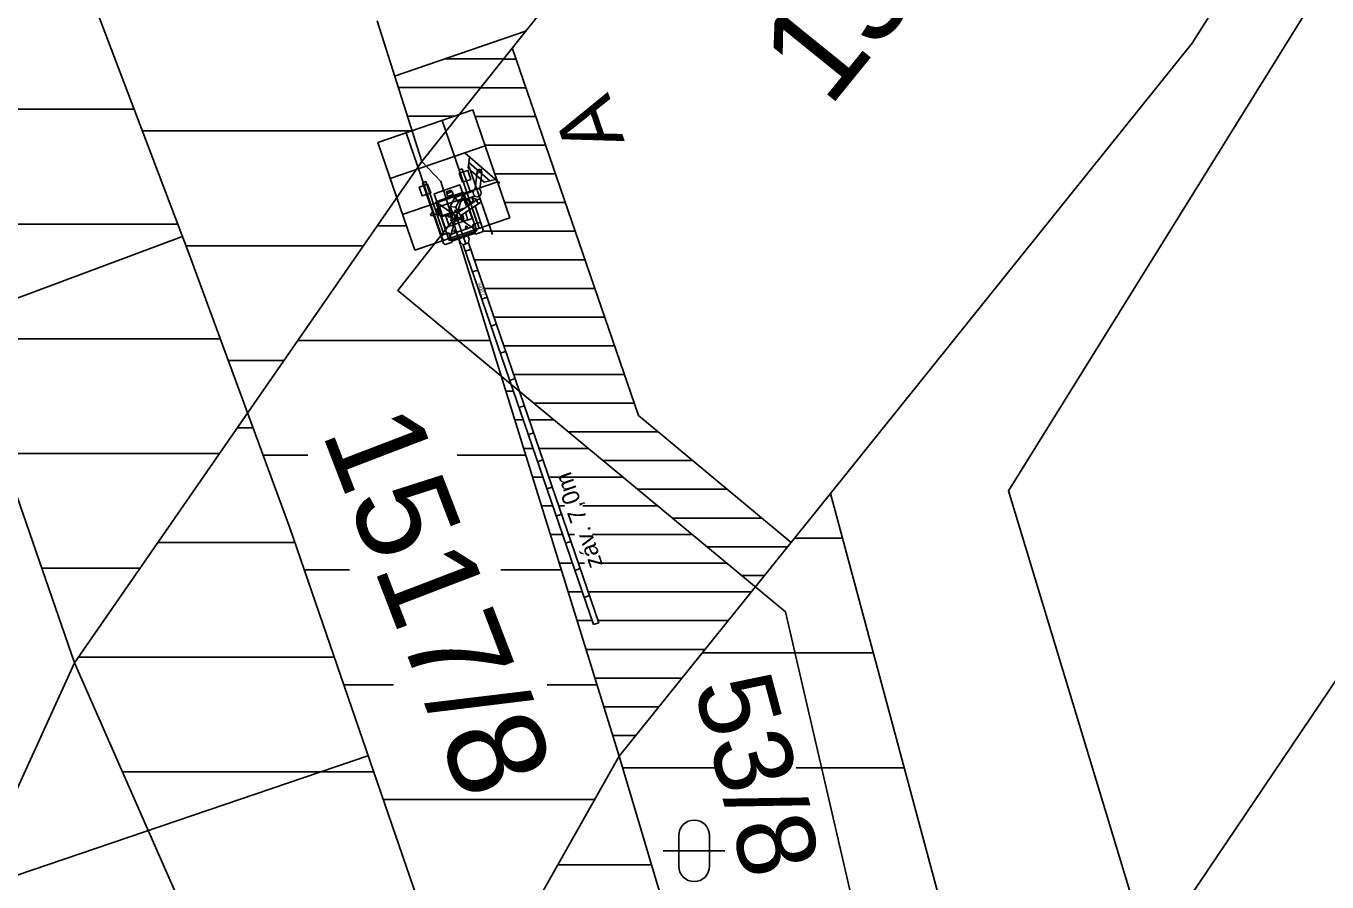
# Model space of a CAD drawing. Extents: x -553916 to -552953, y -1067470 to -1066637.
# Drawn here: x -553520.24 to -553497.58, y -1066983.52 to -1066968.6 of the extents above; entities that cross this region are included whole.
import ezdxf

# ---------------------------------------------------------------- set-up
doc = ezdxf.new("R2010")
doc.units = 0
for name, color, linetype in [('Hranice parcel', 7, 'Continuous'), ('Kolej', 7, 'Continuous'), ('Nová kabelizace', 7, 'Continuous'), ('nové prvky ZZ', 7, 'Continuous'), ('Parcelní čísla', 7, 'Continuous'), ('Propustek', 7, 'Continuous'), ('Přejezd - štěrkové lože', 7, 'Continuous'), ('trasa_NN_popisky', 7, 'Continuous'), ('Vrstva 1', 7, 'Continuous'), ('Vrstva 58', 7, 'Continuous'), ('Značky kultur', 7, 'Continuous')]:
    doc.layers.add(name, color=color, linetype=linetype)

msp = doc.modelspace()

# ---------------------------------------------------------------- linework, layer by layer
at = {"layer": 'Hranice parcel'}
for p, q in [((-553486.47, -1066947.45), (-553499.93, -1066968.9)), ((-553499.93, -1066968.9), (-553506.23, -1066976.75)), ((-553519.4, -1066979.7), (-553528.66, -1067000.03))]:
    msp.add_line(p, q, dxfattribs=at)
for points in [[(-553489.9, -1066939.2), (-553506.21, -1066961.59), (-553507.62, -1066963.64), (-553510.49, -1066967.37), (-553513.35, -1066970.96)], [(-553481.25, -1066991.64), (-553501.02, -1066983.66), (-553503.13, -1066976.7), (-553485.37, -1066948.09)]]:
    msp.add_lwpolyline(points, dxfattribs=at)
at = {"layer": 'Kolej'}
msp.add_lwpolyline([(-553503.324, -1067065.808), (-553502.678, -1067054.027), (-553502.762, -1067041.504), (-553503.626, -1067029.057), (-553504.756, -1067019.974), (-553506.183, -1067011.388), (-553508.328, -1067001.388), (-553510.948, -1066991.622), (-553512.921, -1066985.291), (-553515.647, -1066977.347), (-553517.422, -1066972.53), (-553519.157, -1066967.95), (-553522.886, -1066958.375), (-553529.101, -1066942.549), (-553538.686, -1066918.107), (-553542.908, -1066907.329), (-553546.692, -1066897.676), (-553555.025, -1066876.441), (-553564.644, -1066851.894), (-553574.241, -1066827.427), (-553583.19, -1066804.618)], dxfattribs=at)
at = {"layer": 'Nová kabelizace'}
msp.add_line((-553505.478, -1066985.448), (-553507.017, -1066978.813), dxfattribs=at)
for points in [[(-553507.017, -1066978.813), (-553513.769, -1066973.209), (-553512.749, -1066971.917)], [(-553506.913, -1066977.6), (-553509.575, -1066975.39)]]:
    msp.add_lwpolyline(points, dxfattribs=at)
at = {"layer": 'nové prvky ZZ'}
for p, q in [((-553512.461, -1066970.063), (-553514.116, -1066970.631)), ((-553512.461, -1066970.063), (-553511.816, -1066971.941)), ((-553512.349, -1066972.124), (-553512.993, -1066970.246)), ((-553512.975, -1066972.339), (-553513.62, -1066970.461)), ((-553514.116, -1066970.631), (-553513.471, -1066972.509)), ((-553512.246, -1066970.689), (-553513.901, -1066971.257)), ((-553512.595, -1066970.814), (-553511.991, -1066971.338)), ((-553512.52, -1066970.88), (-553512.54, -1066971.079)), ((-553512.53, -1066970.979), (-553512.163, -1066971.297)), ((-553512.528, -1066971.045), (-553512.119, -1066972.237)), ((-553512.7, -1066971.109), (-553512.644, -1066971.09)), ((-553512.56, -1066971.518), (-553512.7, -1066971.109)), ((-553512.504, -1066971.499), (-553512.644, -1066971.09)), ((-553512.54, -1066971.079), (-553512.261, -1066971.321)), ((-553512.385, -1066971.135), (-553512.421, -1066971.443)), ((-553512.293, -1066971.076), (-553512.4, -1066971.2)), ((-553512.355, -1066971.139), (-553512.338, -1066971.137)), ((-553512.345, -1066971.146), (-553512.348, -1066971.13)), ((-553512.306, -1066971.145), (-553512.341, -1066971.451)), ((-553512.066, -1066971.273), (-553512.261, -1066971.321)), ((-553512.031, -1066971.315), (-553513.686, -1066971.883)), ((-553513.282, -1066971.308), (-553513.337, -1066971.328)), ((-553512.971, -1066972.394), (-553513.337, -1066971.328)), ((-553512.964, -1066972.234), (-553513.282, -1066971.308)), ((-553513.106, -1066971.666), (-553512.624, -1066971.499)), ((-553513.05, -1066971.646), (-553512.624, -1066971.499)), ((-553512.91, -1066971.521), (-553512.912, -1066971.522)), ((-553512.875, -1066972.337), (-553512.624, -1066971.499)), ((-553512.453, -1066971.481), (-553512.775, -1066971.592)), ((-553512.393, -1066972.17), (-553512.624, -1066971.499)), ((-553512.875, -1066972.337), (-553513.105, -1066971.665)), ((-553513.105, -1066971.665), (-553512.393, -1066972.17)), ((-553513.043, -1066971.751), (-553512.993, -1066971.897)), ((-553512.775, -1066971.592), (-553512.853, -1066971.748)), ((-553512.853, -1066971.748), (-553512.811, -1066971.868)), ((-553512.853, -1066971.748), (-553512.757, -1066971.756)), ((-553512.775, -1066971.592), (-553512.713, -1066971.663)), ((-553512.713, -1066971.663), (-553512.757, -1066971.756)), ((-553512.377, -1066971.624), (-553512.717, -1066971.853)), ((-553512.713, -1066971.663), (-553512.427, -1066971.565)), ((-553512.336, -1066971.681), (-553512.677, -1066971.91)), ((-553512.609, -1066971.628), (-553512.567, -1066971.752)), ((-553512.587, -1066971.659), (-553512.557, -1066971.745)), ((-553512.557, -1066971.744), (-553512.552, -1066971.733)), ((-553512.496, -1066971.704), (-553512.531, -1066971.601)), ((-553512.506, -1066971.675), (-553512.469, -1066971.663)), ((-553512.445, -1066971.67), (-553512.476, -1066971.582)), ((-553512.469, -1066971.663), (-553512.461, -1066971.657)), ((-553512.461, -1066971.657), (-553512.454, -1066971.644)), ((-553512.422, -1066971.607), (-553512.434, -1066971.611)), ((-553512.411, -1066971.64), (-553512.423, -1066971.644)), ((-553512.421, -1066971.611), (-553512.422, -1066971.607)), ((-553512.278, -1066972.156), (-553512.422, -1066971.738)), ((-553512.414, -1066971.609), (-553512.421, -1066971.611)), ((-553512.414, -1066971.609), (-553512.405, -1066971.633)), ((-553512.405, -1066971.633), (-553512.412, -1066971.636)), ((-553512.412, -1066971.636), (-553512.411, -1066971.64)), ((-553511.816, -1066971.941), (-553513.471, -1066972.509)), ((-553513.201, -1066971.879), (-553513.194, -1066971.877)), ((-553513.201, -1066971.879), (-553513.192, -1066971.903)), ((-553513.195, -1066971.873), (-553513.183, -1066971.869)), ((-553513.194, -1066971.877), (-553513.195, -1066971.873)), ((-553513.192, -1066971.903), (-553513.185, -1066971.901)), ((-553513.185, -1066971.901), (-553513.184, -1066971.905)), ((-553513.184, -1066971.905), (-553513.172, -1066971.901)), ((-553513.134, -1066971.888), (-553513.147, -1066971.882)), ((-553513.124, -1066971.888), (-553513.134, -1066971.888)), ((-553513.087, -1066971.875), (-553513.124, -1066971.888)), ((-553513.079, -1066971.816), (-553513.058, -1066971.878)), ((-553513.056, -1066971.755), (-553513.007, -1066971.899)), ((-553513.021, -1066971.894), (-553512.944, -1066972.12)), ((-553513.007, -1066971.899), (-553512.995, -1066971.912)), ((-553512.995, -1066971.912), (-553512.977, -1066971.913)), ((-553512.993, -1066971.897), (-553512.98, -1066971.902)), ((-553512.98, -1066971.902), (-553512.819, -1066971.846)), ((-553512.977, -1066971.913), (-553512.815, -1066971.857)), ((-553512.871, -1066972.089), (-553512.936, -1066971.899)), ((-553512.907, -1066971.888), (-553512.898, -1066971.914)), ((-553512.898, -1066971.914), (-553512.891, -1066971.922)), ((-553512.895, -1066971.884), (-553512.885, -1066971.916)), ((-553512.891, -1066971.922), (-553512.882, -1066971.927)), ((-553512.885, -1066971.916), (-553512.876, -1066971.916)), ((-553512.882, -1066971.927), (-553512.873, -1066971.927)), ((-553512.876, -1066971.916), (-553512.85, -1066971.907)), ((-553512.873, -1066971.927), (-553512.84, -1066971.916)), ((-553512.871, -1066972.089), (-553512.546, -1066971.978)), ((-553512.851, -1066971.92), (-553512.83, -1066971.981)), ((-553512.842, -1066971.911), (-553512.819, -1066971.977)), ((-553512.8, -1066971.856), (-553512.763, -1066971.83)), ((-553512.717, -1066971.906), (-553512.782, -1066971.929)), ((-553512.769, -1066971.848), (-553512.757, -1066971.84)), ((-553512.76, -1066971.885), (-553512.738, -1066971.95)), ((-553512.759, -1066971.82), (-553512.743, -1066971.808)), ((-553512.757, -1066971.756), (-553512.734, -1066971.823)), ((-553512.745, -1066971.916), (-553512.754, -1066971.919)), ((-553512.748, -1066971.922), (-553512.751, -1066971.913)), ((-553512.749, -1066971.917), (-553512.585, -1066972.397)), ((-553512.73, -1066971.829), (-553512.746, -1066971.84)), ((-553512.743, -1066971.808), (-553512.73, -1066971.829)), ((-553512.736, -1066971.818), (-553512.591, -1066971.768)), ((-553512.731, -1066971.828), (-553512.628, -1066971.793)), ((-553512.731, -1066971.83), (-553512.725, -1066971.849)), ((-553512.71, -1066971.986), (-553512.674, -1066971.964)), ((-553512.693, -1066971.963), (-553512.681, -1066971.955)), ((-553512.658, -1066971.931), (-553512.677, -1066971.944)), ((-553512.673, -1066971.908), (-553512.668, -1066971.925)), ((-553512.664, -1066971.964), (-553512.645, -1066971.951)), ((-553512.663, -1066971.901), (-553512.656, -1066971.921)), ((-553512.645, -1066971.951), (-553512.658, -1066971.931)), ((-553512.546, -1066971.978), (-553512.589, -1066971.851)), ((-553512.541, -1066971.976), (-553512.546, -1066971.978)), ((-553512.539, -1066971.981), (-553512.541, -1066971.976)), ((-553512.47, -1066971.957), (-553512.539, -1066971.981)), ((-553512.47, -1066971.957), (-553512.522, -1066971.806)), ((-553512.383, -1066972.035), (-553512.472, -1066971.773)), ((-553512.879, -1066972.205), (-553512.998, -1066972.246)), ((-553512.944, -1066972.12), (-553512.874, -1066972.096)), ((-553512.867, -1066972.238), (-553512.879, -1066972.205)), ((-553512.876, -1066972.091), (-553512.871, -1066972.089)), ((-553512.874, -1066972.096), (-553512.876, -1066972.091)), ((-553512.875, -1066972.337), (-553512.393, -1066972.17)), ((-553512.468, -1066972.064), (-553512.349, -1066972.023)), ((-553512.456, -1066972.097), (-553512.468, -1066972.064)), ((-553512.412, -1066972.226), (-553512.293, -1066972.185)), ((-553512.349, -1066972.023), (-553512.319, -1066972.037)), ((-553512.293, -1066972.185), (-553512.278, -1066972.156)), ((-553512.998, -1066972.246), (-553513.012, -1066972.274)), ((-553512.942, -1066972.408), (-553512.971, -1066972.394)), ((-553512.823, -1066972.367), (-553512.942, -1066972.408)), ((-553512.829, -1066972.35), (-553512.823, -1066972.367)), ((-553512.548, -1066972.254), (-553512.705, -1066972.308)), ((-553512.538, -1066972.381), (-553512.632, -1066972.413)), ((-553512.632, -1066972.413), (-553510.36, -1066979.034)), ((-553512.538, -1066972.381), (-553510.266, -1066979.002)), ((-553512.418, -1066972.209), (-553512.412, -1066972.226)), ((-553512.593, -1066972.525), (-553512.499, -1066972.493)), ((-553512.375, -1066972.854), (-553512.469, -1066972.886)), ((-553512.213, -1066973.327), (-553512.307, -1066973.359)), ((-553512.051, -1066973.8), (-553512.145, -1066973.832)), ((-553511.889, -1066974.273), (-553511.983, -1066974.305)), ((-553511.726, -1066974.746), (-553511.82, -1066974.778)), ((-553511.564, -1066975.218), (-553511.658, -1066975.251)), ((-553511.402, -1066975.691), (-553511.496, -1066975.724)), ((-553511.239, -1066976.164), (-553511.333, -1066976.197)), ((-553511.077, -1066976.637), (-553511.171, -1066976.67)), ((-553510.915, -1066977.11), (-553511.009, -1066977.142)), ((-553510.753, -1066977.583), (-553510.847, -1066977.615)), ((-553510.59, -1066978.056), (-553510.684, -1066978.088)), ((-553510.428, -1066978.529), (-553510.522, -1066978.561)), ((-553510.266, -1066979.002), (-553510.36, -1066979.034))]:
    msp.add_line(p, q, dxfattribs=at)
for points in [[(-553512.696, -1066971.168), (-553512.643, -1066971.323), (-553512.497, -1066971.273), (-553512.55, -1066971.118)], [(-553513.248, -1066971.357), (-553513.195, -1066971.513), (-553513.341, -1066971.563), (-553513.395, -1066971.408)], [(-553513.136, -1066971.523), (-553513.056, -1066971.755), (-553512.606, -1066971.601), (-553512.686, -1066971.369)], [(-553513.111, -1066971.805), (-553513.076, -1066971.908), (-553513.063, -1066971.903), (-553513.098, -1066971.801)], [(-553513.069, -1066971.77), (-553513.053, -1066971.819), (-553513.036, -1066971.813), (-553513.053, -1066971.764)], [(-553512.848, -1066971.904), (-553512.851, -1066971.896), (-553512.833, -1066971.89), (-553512.83, -1066971.898)], [(-553512.649, -1066971.979), (-553512.644, -1066971.994), (-553512.621, -1066971.987), (-553512.627, -1066971.972)], [(-553512.867, -1066972.238), (-553512.829, -1066972.35), (-553512.418, -1066972.209), (-553512.456, -1066972.097)], [(-553512.811, -1066972.035), (-553512.806, -1066972.05), (-553512.784, -1066972.043), (-553512.789, -1066972.027)]]:
    msp.add_lwpolyline(points, close=True, dxfattribs=at)
for points in [[(-553512.869, -1066971.473), (-553512.92, -1066971.491), (-553512.91, -1066971.521), (-553512.858, -1066971.503), (-553512.865, -1066971.484)], [(-553512.912, -1066971.522), (-553512.896, -1066971.57), (-553512.802, -1066971.537), (-553512.82, -1066971.483), (-553512.86, -1066971.497)], [(-553512.865, -1066971.484), (-553512.838, -1066971.475), (-553512.841, -1066971.464), (-553512.869, -1066971.473)], [(-553512.582, -1066971.618), (-553512.57, -1066971.653), (-553512.587, -1066971.659), (-553512.599, -1066971.624)], [(-553512.526, -1066971.724), (-553512.552, -1066971.733), (-553512.579, -1066971.656)], [(-553512.559, -1066971.61), (-553512.551, -1066971.635)], [(-553512.551, -1066971.635), (-553512.534, -1066971.629), (-553512.512, -1066971.691), (-553512.53, -1066971.697)], [(-553512.506, -1066971.711), (-553512.54, -1066971.609), (-553512.53, -1066971.606), (-553512.496, -1066971.704)], [(-553512.53, -1066971.697), (-553512.521, -1066971.721)], [(-553512.44, -1066971.667), (-553512.446, -1066971.669), (-553512.467, -1066971.606), (-553512.458, -1066971.602), (-553512.454, -1066971.614)], [(-553512.454, -1066971.614), (-553512.435, -1066971.607), (-553512.434, -1066971.611)], [(-553512.423, -1066971.644), (-553512.421, -1066971.648), (-553512.44, -1066971.654)], [(-553512.44, -1066971.654), (-553512.436, -1066971.665)], [(-553513.166, -1066971.858), (-553513.185, -1066971.864), (-553513.183, -1066971.869)], [(-553513.172, -1066971.901), (-553513.171, -1066971.905), (-553513.152, -1066971.899)], [(-553513.152, -1066971.899), (-553513.148, -1066971.91), (-553513.139, -1066971.907), (-553513.16, -1066971.843), (-553513.17, -1066971.847), (-553513.166, -1066971.858)], [(-553513.079, -1066971.816), (-553513.091, -1066971.82), (-553513.07, -1066971.882), (-553513.058, -1066971.878)], [(-553513.065, -1066971.783), (-553513.088, -1066971.791), (-553513.079, -1066971.816)], [(-553513.058, -1066971.878), (-553513.049, -1066971.904), (-553513.017, -1066971.893), (-553513.043, -1066971.815)], [(-553512.827, -1066971.9), (-553512.828, -1066971.897), (-553512.853, -1066971.906), (-553512.85, -1066971.914), (-553512.828, -1066971.906)], [(-553512.806, -1066971.973), (-553512.846, -1066971.986), (-553512.843, -1066971.995), (-553512.799, -1066971.98), (-553512.799, -1066971.98)], [(-553512.754, -1066971.845), (-553512.772, -1066971.818), (-553512.764, -1066971.813), (-553512.743, -1066971.845)], [(-553512.684, -1066971.949), (-553512.666, -1066971.977), (-553512.659, -1066971.971), (-553512.68, -1066971.939)], [(-553512.68, -1066971.94), (-553512.662, -1066971.934)], [(-553512.658, -1066971.932), (-553512.625, -1066971.921), (-553512.628, -1066971.911), (-553512.678, -1066971.928)], [(-553512.66, -1066971.973), (-553512.657, -1066971.982), (-553512.619, -1066971.969), (-553512.634, -1066971.924)], [(-553512.798, -1066971.98), (-553512.835, -1066971.993), (-553512.82, -1066972.038), (-553512.781, -1066972.025), (-553512.796, -1066971.982)], [(-553512.766, -1066972.163), (-553512.761, -1066972.161), (-553512.749, -1066972.197), (-553512.776, -1066972.207), (-553512.789, -1066972.171), (-553512.784, -1066972.169)], [(-553512.784, -1066972.169), (-553512.787, -1066972.161), (-553512.769, -1066972.155), (-553512.766, -1066972.163)], [(-553512.567, -1066972.095), (-553512.562, -1066972.093), (-553512.55, -1066972.129), (-553512.578, -1066972.139), (-553512.59, -1066972.103), (-553512.585, -1066972.101)], [(-553512.585, -1066972.101), (-553512.588, -1066972.093), (-553512.57, -1066972.087), (-553512.567, -1066972.095)], [(-553512.632, -1066972.413), (-553512.683, -1066972.367), (-553512.703, -1066972.307)], [(-553512.538, -1066972.381), (-553512.526, -1066972.313), (-553512.546, -1066972.253)]]:
    msp.add_lwpolyline(points, dxfattribs=at)
for centre, radius in [((-553512.347, -1066971.138), 0.00856), ((-553512.386, -1066971.506), 0.0716), ((-553512.356, -1066971.653), 0.0347), ((-553512.749, -1066971.917), 0.0725)]:
    msp.add_circle(centre, radius, dxfattribs=at)
for centre, radius, start, end in [((-553512.345, -1066971.14), 0.0399, 353.2567, 174.9637), ((-553512.749, -1066971.917), 0.0795, 129.387, 299.921)]:
    msp.add_arc(centre, radius, start, end, dxfattribs=at)
at = {"layer": 'Propustek'}
for p, q in [((-553514.85, -1066990.05), (-553509.91, -1066981.33)), ((-553510.982, -1066983.222), (-553509.346, -1066983.222))]:
    msp.add_line(p, q, dxfattribs=at)
for points in [[(-553576.56, -1066984.514), (-553536.119, -1066969.402), (-553529.408, -1066976.709), (-553517.537, -1066972.276)], [(-553509.91, -1066981.33), (-553508.76, -1066985.19), (-553504.27, -1066984.05)]]:
    msp.add_lwpolyline(points, dxfattribs=at)
at = {"layer": 'Přejezd - štěrkové lože'}
msp.add_lwpolyline([(-553573.367, -1066993.961), (-553535.151, -1066981.6), (-553526.82, -1066985.587), (-553514.291, -1066981.32)], dxfattribs=at)
at = {"layer": 'trasa_NN_popisky'}
msp.add_lwpolyline([(-553456.479, -1066963.507), (-553494.623, -1066975.849), (-553504.368, -1066990.297)], dxfattribs=at)
at = {"layer": 'Vrstva 1'}
for p, q in [((-553514.13, -1066968.51), (-553513.35, -1066970.96)), ((-553513.823, -1066969.473), (-553511.542, -1066968.69)), ((-553511.774, -1066968.982), (-553509.575, -1066975.39)), ((-553512.948, -1066969.173), (-553511.926, -1066969.173)), ((-553511.929, -1066969.176), (-553511.708, -1066969.176)), ((-553513.76, -1066969.673), (-553512.325, -1066969.673)), ((-553512.327, -1066969.676), (-553511.536, -1066969.676)), ((-553522.825, -1066970.052), (-553518.361, -1066970.052)), ((-553513.601, -1066970.173), (-553512.781, -1066970.173)), ((-553512.422, -1066970.176), (-553511.365, -1066970.176)), ((-553518.218, -1066970.429), (-553513.519, -1066970.429)), ((-553512.25, -1066970.676), (-553511.193, -1066970.676)), ((-553513.35, -1066970.96), (-553519.4, -1066979.7)), ((-553512.079, -1066971.176), (-553511.021, -1066971.176)), ((-553511.907, -1066971.676), (-553510.85, -1066971.676)), ((-553522.025, -1066972.052), (-553517.603, -1066972.052)), ((-553512.289, -1066972.176), (-553510.678, -1066972.176)), ((-553517.46, -1066972.429), (-553514.367, -1066972.429)), ((-553512.437, -1066972.676), (-553510.507, -1066972.676)), ((-553512.265, -1066973.176), (-553510.335, -1066973.176)), ((-553512.093, -1066973.676), (-553510.164, -1066973.676)), ((-553521.338, -1066974.052), (-553516.861, -1066974.052)), ((-553511.922, -1066974.176), (-553509.992, -1066974.176)), ((-553516.722, -1066974.429), (-553515.751, -1066974.429)), ((-553511.75, -1066974.676), (-553509.82, -1066974.676)), ((-553511.886, -1066974.965), (-553511.756, -1066974.965)), ((-553511.4, -1066975.176), (-553509.649, -1066975.176)), ((-553511.73, -1066975.465), (-553511.584, -1066975.465)), ((-553511.479, -1066975.465), (-553511.051, -1066975.465)), ((-553510.797, -1066975.676), (-553509.231, -1066975.676)), ((-553520.656, -1066976.052), (-553516.875, -1066976.052)), ((-553511.575, -1066975.965), (-553511.413, -1066975.965)), ((-553511.308, -1066975.965), (-553510.449, -1066975.965)), ((-553510.195, -1066976.176), (-553508.629, -1066976.176)), ((-553519.4, -1066979.7), (-553520.52, -1066976.45)), ((-553511.42, -1066976.465), (-553511.241, -1066976.465)), ((-553511.136, -1066976.465), (-553509.846, -1066976.465)), ((-553509.592, -1066976.676), (-553508.026, -1066976.676)), ((-553511.265, -1066976.965), (-553511.07, -1066976.965)), ((-553510.965, -1066976.965), (-553510.865, -1066976.965)), ((-553510.547, -1066976.965), (-553509.244, -1066976.965)), ((-553509.91, -1066981.33), (-553506.23, -1066976.75)), ((-553506.23, -1066976.75), (-553504.27, -1066984.05)), ((-553508.99, -1066977.176), (-553507.424, -1066977.176)), ((-553511.11, -1066977.465), (-553510.898, -1066977.465)), ((-553510.793, -1066977.465), (-553510.691, -1066977.465)), ((-553510.374, -1066977.465), (-553508.641, -1066977.465)), ((-553508.387, -1066977.676), (-553506.974, -1066977.676)), ((-553519.968, -1066978.052), (-553518.259, -1066978.052)), ((-553510.954, -1066977.965), (-553510.727, -1066977.965)), ((-553510.622, -1066977.965), (-553510.518, -1066977.965)), ((-553510.2, -1066977.965), (-553508.039, -1066977.965)), ((-553507.784, -1066978.176), (-553507.376, -1066978.176)), ((-553510.799, -1066978.465), (-553510.555, -1066978.465)), ((-553510.45, -1066978.465), (-553507.608, -1066978.465)), ((-553510.644, -1066978.965), (-553510.383, -1066978.965)), ((-553510.278, -1066978.965), (-553508.01, -1066978.965)), ((-553510.489, -1066979.465), (-553508.411, -1066979.465)), ((-553519.4, -1066979.7), (-553514.85, -1066990.05)), ((-553510.334, -1066979.965), (-553508.813, -1066979.965)), ((-553510.178, -1066980.465), (-553509.215, -1066980.465)), ((-553510.023, -1066980.965), (-553509.617, -1066980.965))]:
    msp.add_line(p, q, dxfattribs=at)
msp.add_lwpolyline([(-553513.35, -1066970.96), (-553513.02, -1066971.31), (-553509.91, -1066981.33)], dxfattribs=at)
at = {"layer": 'Vrstva 58'}
for p, q in [((-553514.126, -1066972.081), (-553513.618, -1066972.081)), ((-553515.51, -1066974.081), (-553512.16, -1066974.081)), ((-553516.564, -1066975.603), (-553516.29, -1066975.603)), ((-553516.114, -1066976.081), (-553515.336, -1066976.081)), ((-553512.731, -1066976.081), (-553511.539, -1066976.081)), ((-553517.948, -1066977.603), (-553515.559, -1066977.603)), ((-553506.855, -1066977.528), (-553506.021, -1066977.528)), ((-553515.395, -1066978.081), (-553514.612, -1066978.081)), ((-553511.972, -1066978.081), (-553510.918, -1066978.081)), ((-553519.333, -1066979.603), (-553514.873, -1066979.603)), ((-553508.462, -1066979.528), (-553505.484, -1066979.528)), ((-553514.709, -1066980.081), (-553513.84, -1066980.081)), ((-553511.167, -1066980.081), (-553510.298, -1066980.081)), ((-553518.563, -1066981.603), (-553514.187, -1066981.603)), ((-553509.851, -1066981.528), (-553508.238, -1066981.528)), ((-553506.83, -1066981.528), (-553504.947, -1066981.528)), ((-553514.023, -1066982.081), (-553510.335, -1066982.081))]:
    msp.add_line(p, q, dxfattribs=at)
at = {"layer": 'Značky kultur'}
for p, q in [((-553508.874, -1066982.708), (-553508.874, -1066983.245)), ((-553508.338, -1066983.245), (-553508.338, -1066982.708)), ((-553509.143, -1066982.977), (-553508.069, -1066982.977))]:
    msp.add_line(p, q, dxfattribs=at)
for centre, start, end in [((-553508.606, -1066982.709), 0, 180), ((-553508.606, -1066983.245), 180, 359.9879)]:
    msp.add_arc(centre, 0.268, start, end, dxfattribs=at)

# ---------------------------------------------------------------- texts
at = {"layer": 'nové prvky ZZ'}
for s, height, rotation, p in [('A', 1.025, 108.8917, (-553509.813, -1066970.609)), ('265', 0.025, 108.9398, (-553512.773, -1066971.948)), ('7,00m', 0.0646, 108.9398, (-553512.243, -1066973.303)), ('záv. 7,0m', 0.3, 109.138, (-553510.19, -1066977.993))]:
    msp.add_text(s, height=height, rotation=rotation, dxfattribs=at).set_placement(p)
at = {"layer": 'Parcelní čísla'}
msp.add_text('1517/1', height=1.7, rotation=51, dxfattribs=at).set_placement((-553506.254, -1066970.044))
at = {"layer": 'Vrstva 1'}
for s, height, rotation, p in [('1517/8', 1.7, 290.9878, (-553515.1, -1066975.676)), ('53/8', 1.36, 285, (-553508.618, -1066980.11))]:
    msp.add_text(s, height=height, rotation=rotation, dxfattribs=at).set_placement(p)

doc.saveas('drawing.dxf')
